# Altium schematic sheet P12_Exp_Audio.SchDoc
size A2
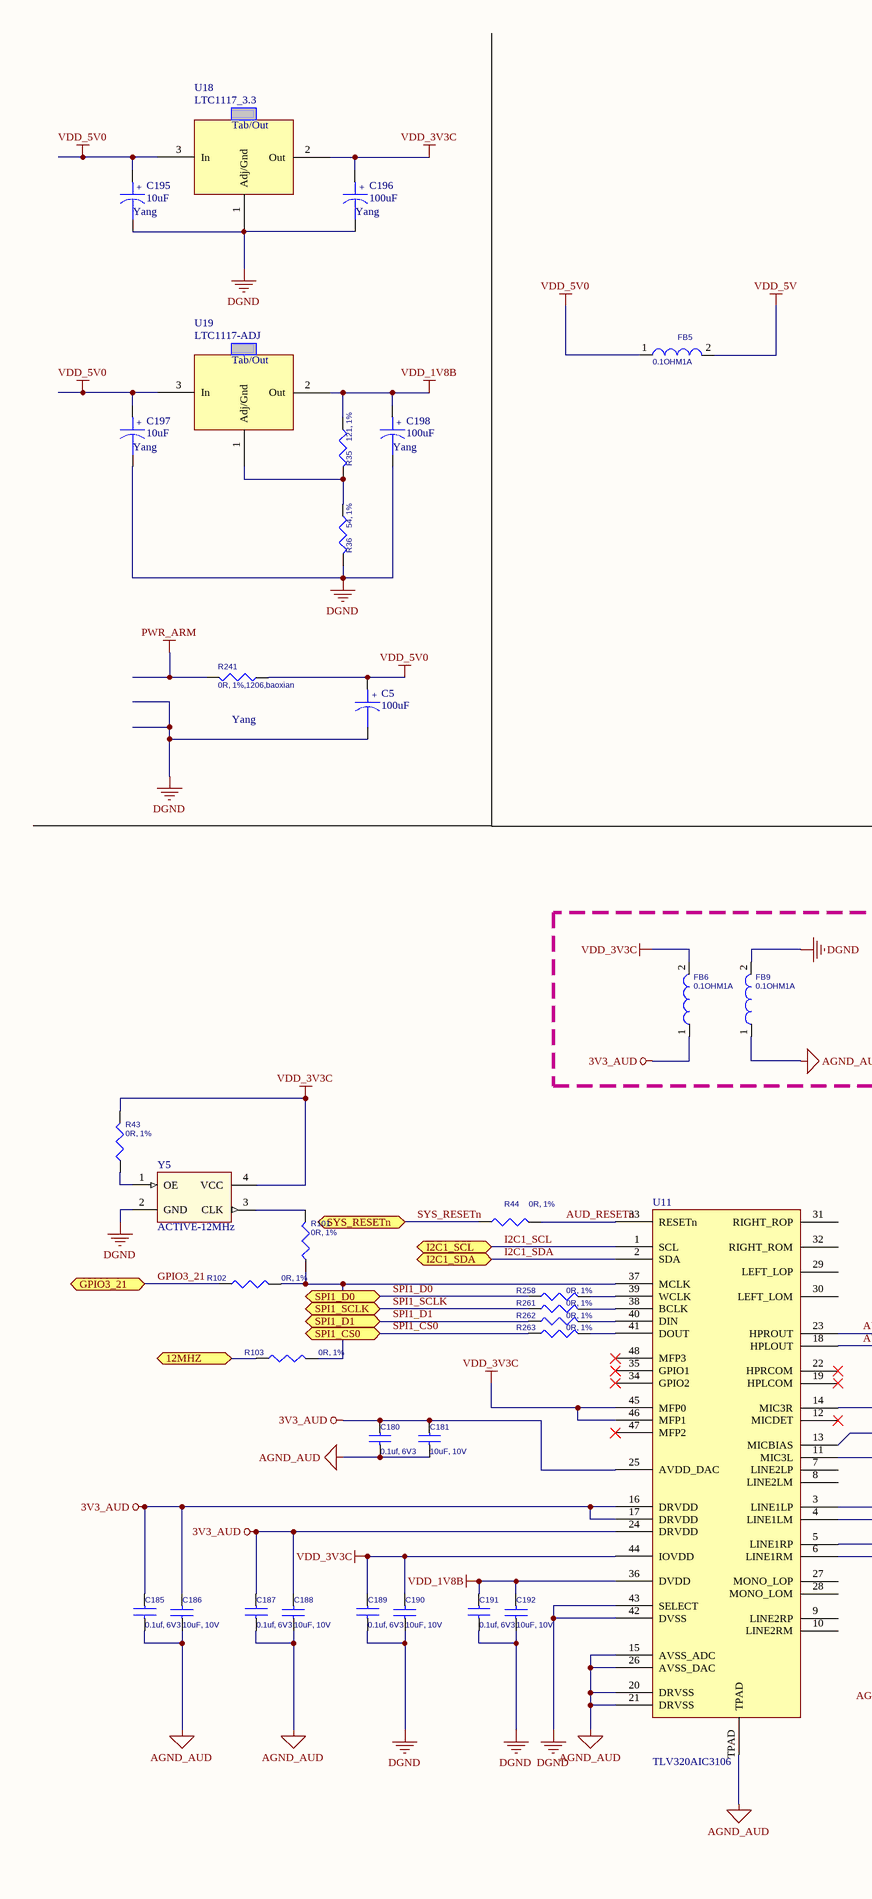
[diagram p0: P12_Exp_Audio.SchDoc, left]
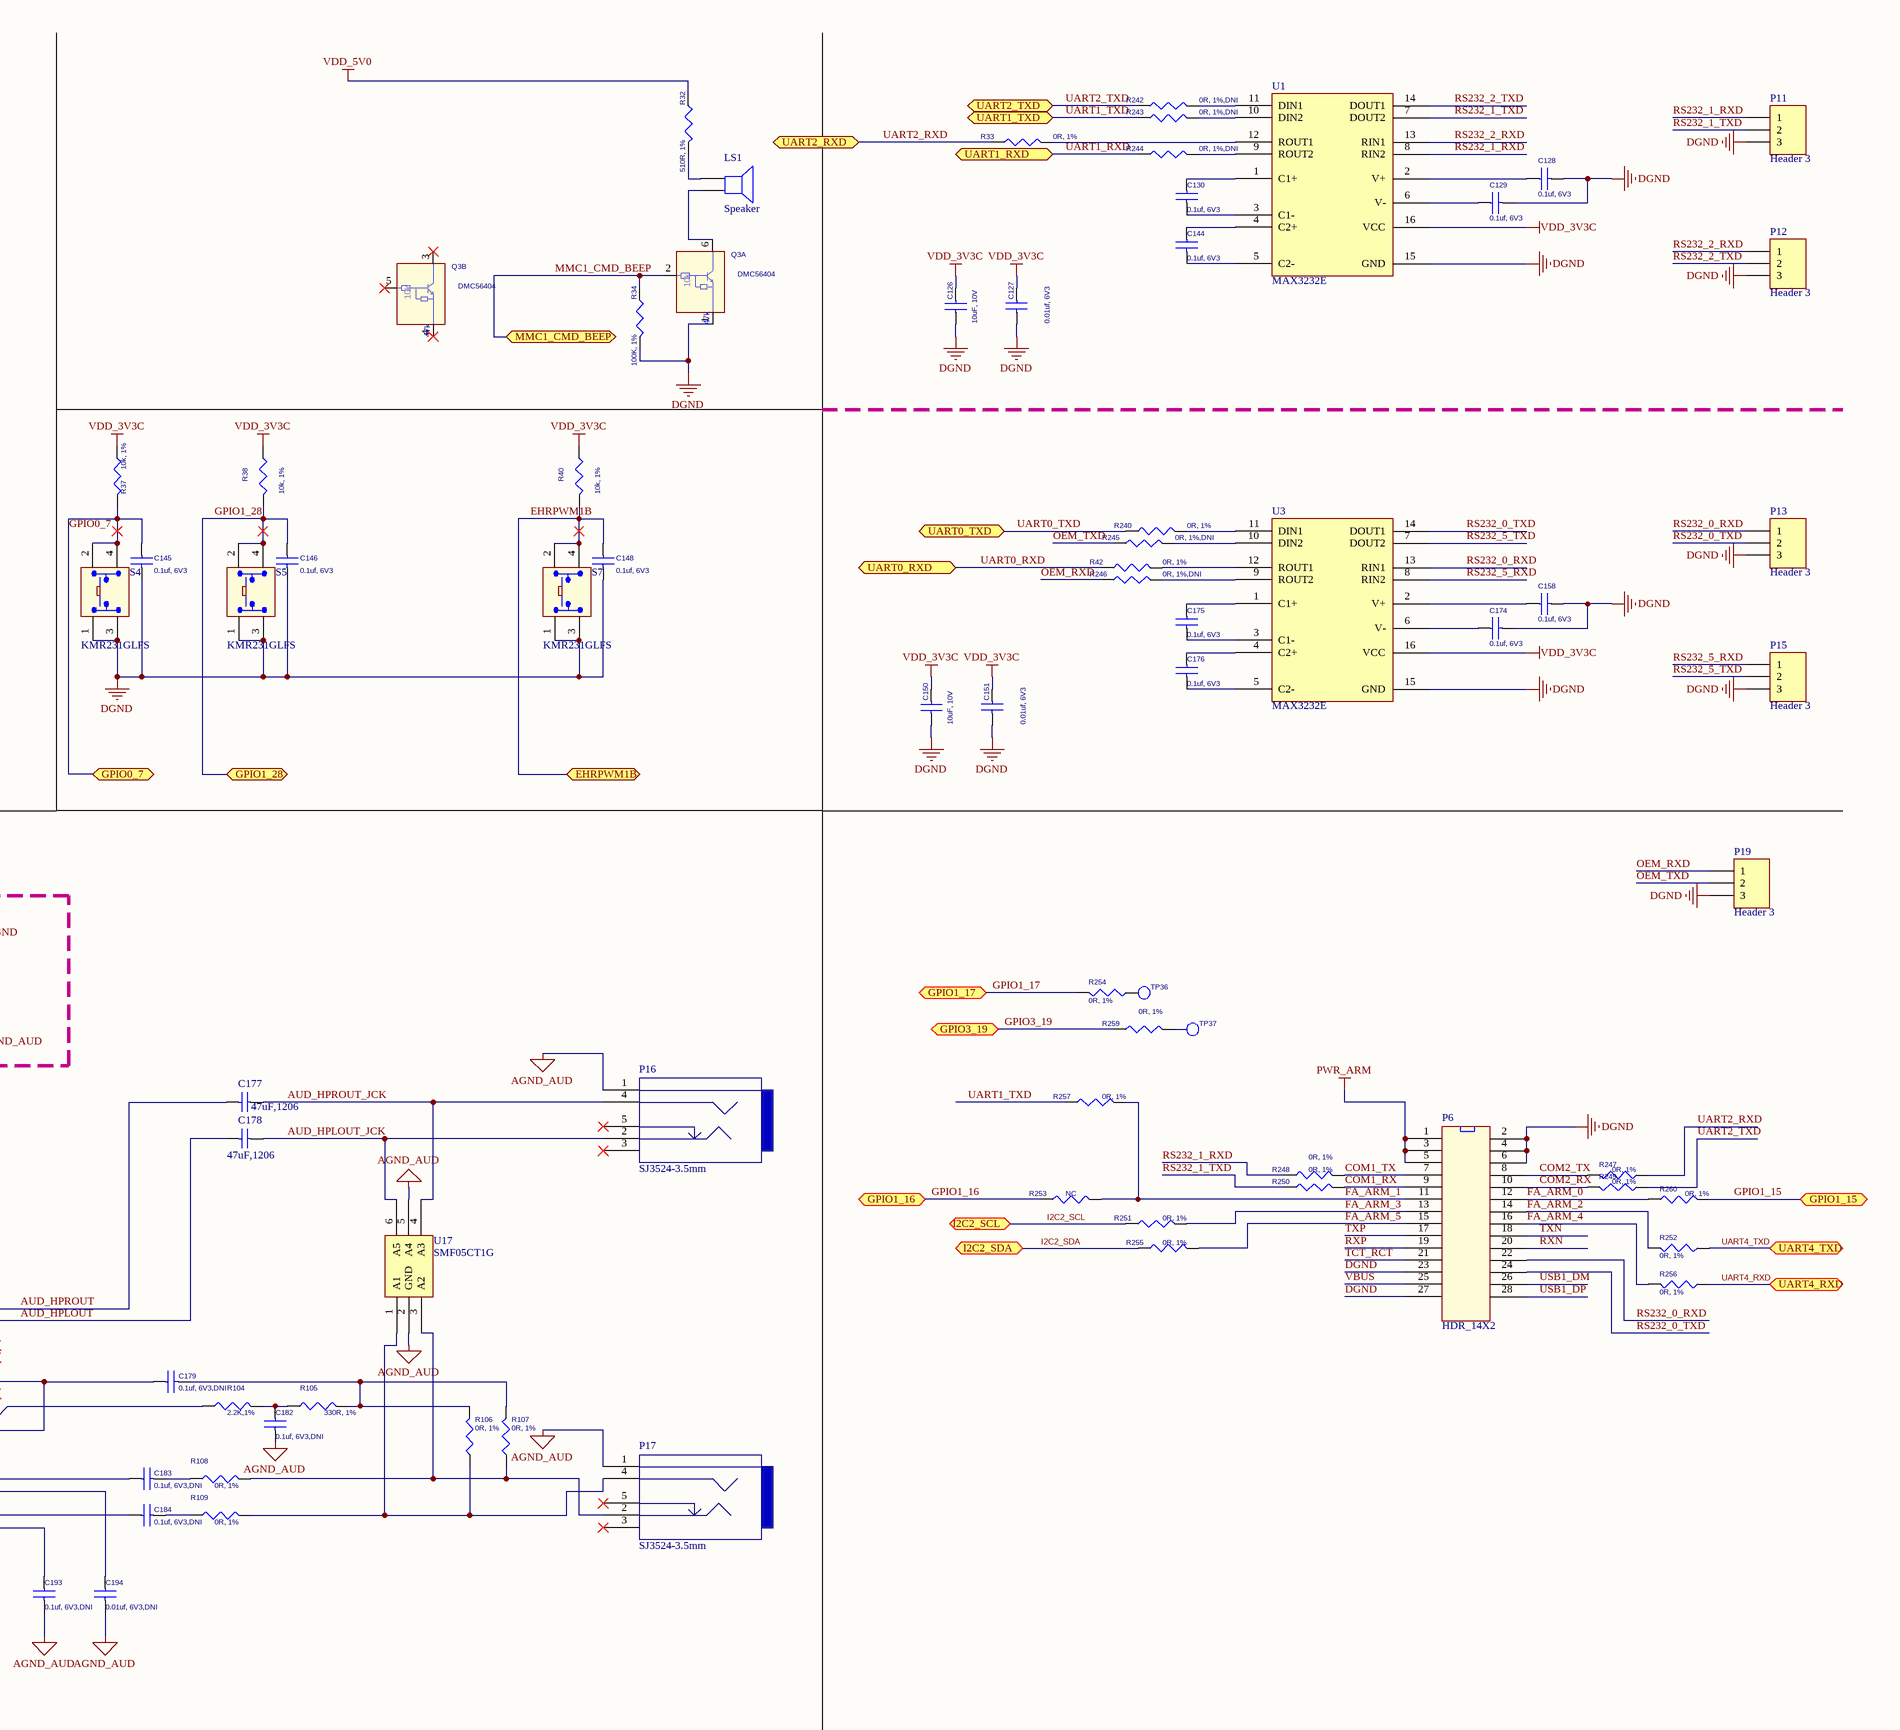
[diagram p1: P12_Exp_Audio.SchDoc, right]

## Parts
C5  100uF  [7343T]
C126  10uF, 10V  [805]
C127  0.01uf, 6V3  [402]
C128  0.1uf, 6V3  [402]
C129  0.1uf, 6V3  [402]
C130  0.1uf, 6V3  [402]
C144  0.1uf, 6V3  [402]
C145  0.1uf, 6V3  [402]
C146  0.1uf, 6V3  [402]
C148  0.1uf, 6V3  [402]
C150  10uF, 10V  [805]
C151  0.01uf, 6V3  [402]
C158  0.1uf, 6V3  [402]
C174  0.1uf, 6V3  [402]
C175  0.1uf, 6V3  [402]
C176  0.1uf, 6V3  [402]
C177  47uF,1206  [1206]
C178  47uF,1206  [1206]
C179  0.1uf, 6V3,DNI  [402]
C180  0.1uf, 6V3  [402]
C181  10uF, 10V  [805]
C182  0.1uf, 6V3,DNI  [402]
C183  0.1uf, 6V3,DNI  [402]
C184  0.1uf, 6V3,DNI  [402]
C185  0.1uf, 6V3  [402]
C186  10uF, 10V  [805]
C187  0.1uf, 6V3  [402]
C188  10uF, 10V  [805]
C189  0.1uf, 6V3  [402]
C190  10uF, 10V  [805]
C191  0.1uf, 6V3  [402]
C192  10uF, 10V  [805]
C193  0.1uf, 6V3,DNI  [402]
C194  0.01uf, 6V3,DNI  [402]
C195  10uF  [3528T]
C196  100uF  [7343T]
C197  10uF  [3528T]
C198  100uF  [7343T]
FB5  0.1OHM1A  [SM-7351-IND-0805]
FB6  0.1OHM1A  [SM-7351-IND-0805]
FB9  0.1OHM1A  [SM-7351-IND-0805]
LS1  Speaker  [PIN2]
P6  HDR_14X2  [HDR_14X2]
P11  Header 3  [HDR1X3]
P12  Header 3  [HDR1X3]
P13  Header 3  [HDR1X3]
P15  Header 3  [HDR1X3]
P16  SJ3524-3.5mm  [jack_audio1]
P17  SJ3524-3.5mm  [jack_audio1]
P19  Header 3  [HDR1X3]
Q3  DMC56404  [SMini6-F3-B]  (parts A,B of 2)
R32  510R, 1%  [R0402]
R33  0R, 1%  [R0603]
R34  100K, 1%  [R0402]
R35  121, 1%  [R0402]
R36  54, 1%  [R0402]
R37  10k, 1%  [R0402]
R38  10k, 1%  [R0402]
R40  10k, 1%  [R0402]
R42  0R, 1%  [R0603]
R43  0R, 1%  [R0402]
R44  0R, 1%  [R0402]
R101  0R, 1%  [R0402]
R102  0R, 1%  [R0402]
R103  0R, 1%  [R0402]
R104  2.2K,1%  [R0402]
R105  330R, 1%  [R0402]
R106  0R, 1%  [R0402]
R107  0R, 1%  [R0402]
R108  0R, 1%  [R0402]
R109  0R, 1%  [R0402]
R240  0R, 1%  [R0603]
R241  0R, 1%,1206,baoxian  [R1206]
R242  0R, 1%,DNI  [R0603]
R243  0R, 1%,DNI  [R0603]
R244  0R, 1%,DNI  [R0603]
R245  0R, 1%,DNI  [R0603]
R246  0R, 1%,DNI  [R0603]
R247  0R, 1%  [R0603]
R248  0R, 1%  [R0603]
R249  0R, 1%  [R0603]
R250  0R, 1%  [R0603]
R251  0R, 1%  [R0603]
R252  0R, 1%  [R0603]
R253  NC  [R0603]
R254  0R, 1%  [R0603]
R255  0R, 1%  [R0603]
R256  0R, 1%  [R0603]
R257  0R, 1%  [R0603]
R258  0R, 1%  [R0603]
R259  0R, 1%  [R0603]
R260  0R, 1%  [R0603]
R261  0R, 1%  [R0603]
R262  0R, 1%  [R0603]
R263  0R, 1%  [R0603]
S4  KMR231GLFS  [SW4SMD_63X161LS]
S5  KMR231GLFS  [SW4SMD_63X161LS]
S7  KMR231GLFS  [SW4SMD_63X161LS]
TP36  TESTPT1  [tp1-8040]  (value not drawn)  (no BOM)
TP37  TESTPT1  [tp1-8040]  (value not drawn)  (no BOM)
U1  MAX3232E  [MAX3232EEA/SSOP16]
U3  MAX3232E  [MAX3232EEA/SSOP16]
U11  TLV320AIC3106  [TLV320AIC3106/QFN-48]
U17  SMF05CT1G  [SMF05CT1G/SC-88]
U18  LTC1117_3.3  [SOT223]
U19  LTC1117-ADJ  [SOT223]
Y5  ACTIVE-12MHz  [OSC4_61X65LS_79X98SMD]

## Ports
12MHZ (bidir), EHRPWM1B (bidir), GPIO0_7 (bidir), GPIO1_15, GPIO1_16, GPIO1_17, GPIO1_28 (bidir), GPIO3_19, GPIO3_21 (bidir), I2C1_SCL (bidir), I2C1_SDA (bidir), I2C2_SCL, I2C2_SDA, MMC1_CMD_BEEP (bidir), SPI1_CS0 (bidir), SPI1_D0 (bidir), SPI1_D1 (bidir), SPI1_SCLK (bidir), SYS_RESETn (bidir), UART0_RXD (bidir), UART0_TXD (bidir), UART1_RXD (bidir), UART1_TXD (bidir), UART2_RXD (bidir), UART2_TXD (bidir), UART4_RXD, UART4_TXD

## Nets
3V3_AUD: C180.1 C181.1 C185.1 C186.2 C187.1 C188.2 FB6.1 U11.16(DRVDD) U11.17(DRVDD) U11.24(DRVDD) U11.25(AVDD_DAC)
AGND_AUD: C180.2 C181.2 C182.2 C185.2 C186.1 C187.2 C188.1 C193.2 C194.2 FB9.1 P16.1 P17.1 U11.15(AVSS_ADC) U11.20(DRVSS) U11.21(DRVSS) U11.26(AVSS_DAC) U11.TPAD U17.2(GND) U17.5(A4)
DGND: C5.2 C126.1 C127.2 C128.2 C129.2 C145.2 C146.2 C148.2 C150.1 C151.2 C158.2 C174.2 C189.2 C190.1 C191.2 C192.1 C195.2 C196.2 C197.2 C198.2 FB9.2 P6.2 P6.4 P6.6 P6.23 P6.27 P11.3 P12.3 P13.3 P15.3 P19.3 Q3.1 R34.2 R36.2 S4.1(A1) S4.3(A3) S5.1(A1) S5.3(A3) S7.1(A1) S7.3(A3) U1.15(GND) U3.15(GND) U11.42(DVSS) U11.43(SELECT) U18.1(Adj/Gnd) Y5.2(GND)
PWR_ARM: P6.1 P6.3 P6.5 R241.2
VDD_1V8B: C191.1 C192.2 C198.1 R35.1 U11.36(DVDD) U19.2(Out)
VDD_3V3C: C126.2 C127.1 C150.2 C151.1 C189.1 C190.2 C196.1 FB6.2 R37.1 R38.1 R40.1 R43.2 U1.16(VCC) U3.16(VCC) U11.44(IOVDD) U11.45(MFP0) U11.46(MFP1) U18.2(Out) Y5.4(VCC)
VDD_5V: FB5.2
VDD_5V0: C5.1 C195.1 C197.1 FB5.1 R32.1 R241.1 U18.3(In) U19.3(In)
12MHZ: R103.1 ; port 12MHZ
AUD_HPLOUT: C178.2 U11.18(HPLOUT)
AUD_HPLOUT_JCK: C178.1 P16.2 U17.6(A5)
AUD_HPROUT: C177.2 U11.23(HPROUT)
AUD_HPROUT_JCK: C177.1 P16.4 U17.4(A3)
AUD_RESETn: R44.2 U11.33(RESETn)
COM1_RX: P6.9 R250.2
COM1_TX: P6.7 R248.2
COM2_RX: P6.10 R249.2
COM2_TX: P6.8 R247.2
EHRPWM1B: C148.1 R40.2 S7.2(A2) S7.4 ; port EHRPWM1B
FA_ARM_0: P6.12 R260.1
FA_ARM_1: P6.11 R253.2 R257.2
FA_ARM_2: P6.14 R252.2
FA_ARM_3: P6.13 R251.2
FA_ARM_4: P6.16 R256.2
FA_ARM_5: P6.15 R255.2
GPIO0_7: C145.1 R37.2 S4.2(A2) S4.4 ; port GPIO0_7
GPIO1_15: R260.2 ; port GPIO1_15
GPIO1_16: R253.1 ; port GPIO1_16
GPIO1_17: R254.2 ; port GPIO1_17
GPIO1_28: C146.1 R38.2 S5.2(A2) S5.4 ; port GPIO1_28
GPIO3_19: R259.1 ; port GPIO3_19
GPIO3_21: R102.1 ; port GPIO3_21
I2C1_SCL: U11.1(SCL) ; port I2C1_SCL
I2C1_SDA: U11.2(SDA) ; port I2C1_SDA
I2C2_SCL: R251.1 ; port I2C2_SCL
I2C2_SDA: R255.1 ; port I2C2_SDA
MMC1_CMD_BEEP: Q3.2 R34.1 ; port MMC1_CMD_BEEP
OEM_RXD: P19.1 R246.1
OEM_TXD: P19.2 R245.1
RS232_0_RXD: P6.22 P13.1 U3.13(RIN1)
RS232_0_TXD: P6.24 P13.2 U3.14(DOUT1)
RS232_1_RXD: P11.1 R248.1 U1.8(RIN2)
RS232_1_TXD: P11.2 R250.1 U1.7(DOUT2)
RS232_2_RXD: P12.1 U1.13(RIN1)
RS232_2_TXD: P12.2 U1.14(DOUT1)
RS232_5_RXD: P15.1 U3.8(RIN2)
RS232_5_TXD: P15.2 U3.7(DOUT2)
RXN: P6.20
RXP: P6.19
SPI1_CS0: R263.1 ; port SPI1_CS0
SPI1_D0: R258.1 ; port SPI1_D0
SPI1_D1: R262.1 ; port SPI1_D1
SPI1_SCLK: R261.1 ; port SPI1_SCLK
SYS_RESETn: R44.1 ; port SYS_RESETn
TCT_RCT: P6.21
TXN: P6.18
TXP: P6.17
UART0_RXD: R42.1 ; port UART0_RXD
UART0_TXD: R240.1 ; port UART0_TXD
UART1_RXD: R244.1 ; port UART1_RXD
UART1_TXD: R243.1 R257.1 ; port UART1_TXD
UART2_RXD: R33.1 R247.1 ; port UART2_RXD
UART2_TXD: R242.1 R249.1 ; port UART2_TXD
UART4_RXD: R256.1 ; port UART4_RXD
UART4_TXD: R252.1 ; port UART4_TXD
USB1_DM: P6.26
USB1_DP: P6.28
VBUS: P6.25
NetC128_1: C128.1 U1.2(V+)
NetC129_1: C129.1 U1.6(V-)
NetC130_1: C130.1 U1.1(C1+)
NetC130_2: C130.2 U1.3(C1-)
NetC144_1: C144.1 U1.4(C2+)
NetC144_2: C144.2 U1.5(C2-)
NetC158_1: C158.1 U3.2(V+)
NetC174_1: C174.1 U3.6(V-)
NetC175_1: C175.1 U3.1(C1+)
NetC175_2: C175.2 U3.3(C1-)
NetC176_1: C176.1 U3.4(C2+)
NetC176_2: C176.2 U3.5(C2-)
NetC179_1: C179.1 U11.11(MIC3L) U11.14(MIC3R)
NetC179_2: C179.2 R105.2 R106.2 R107.2
NetC182_1: C182.1 R104.2 R105.1
NetC183_1: C183.1 U11.3(LINE1LP)
NetC183_2: C183.2 R108.1
NetC184_1: C184.1 U11.5(LINE1RP)
NetC184_2: C184.2 R109.1
NetC193_1: C193.1 U11.6(LINE1RM)
NetC194_1: C194.1 U11.4(LINE1LM)
NetLS1_1: LS1.1 R32.2
NetLS1_2: LS1.2 Q3.6
NetP17_2: P17.2 R107.1 R108.2 U17.3(A2)
NetP17_4: P17.4 R106.1 R109.2 U17.1(A1)
NetR33_2: R33.2 U1.12(ROUT1)
NetR35_2: R35.2 R36.1 U19.1(Adj/Gnd)
NetR42_2: R42.2 U3.12(ROUT1)
NetR43_1: R43.1 Y5.1(OE)
NetR101_1: R101.1 R102.2 R103.2 U11.37(MCLK)
NetR101_2: R101.2 Y5.3(CLK)
NetR104_1: R104.1 U11.13(MICBIAS)
NetR240_2: R240.2 U3.11(DIN1)
NetR242_2: R242.2 U1.11(DIN1)
NetR243_2: R243.2 U1.10(DIN2)
NetR244_2: R244.2 U1.9(ROUT2)
NetR245_2: R245.2 U3.10(DIN2)
NetR246_2: R246.2 U3.9(ROUT2)
NetR254_1: R254.1 TP36.1(TP)
NetR258_2: R258.2 U11.39(WCLK)
NetR259_2: R259.2 TP37.1(TP)
NetR261_2: R261.2 U11.38(BCLK)
NetR262_2: R262.2 U11.40(DIN)
NetR263_2: R263.2 U11.41(DOUT)

Not connected (* = marked no-connect by the designer): P16 3* 5*; P17 3* 5*; Q3 3* 4* 5*; U11 7(LINE2LP) 8(LINE2LM) 9(LINE2RP) 10(LINE2RM) 12(MICDET)* 19(HPLCOM)* 22(HPRCOM)* 27(MONO_LOP) 28(MONO_LOM) 29(LEFT_LOP) 30(LEFT_LOM) 31(RIGHT_ROP) 32(RIGHT_ROM) 34(GPIO2)* 35(GPIO1)* 47(MFP2)* 48(MFP3)*

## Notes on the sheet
- (near C195) Yang
- (near C196) Yang
- (near C197) Yang
- (near C198) Yang
- (near R241) Yang

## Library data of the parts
C5 C195-C198 = CAPACITOR POL: Capacitor
C126 C150 C181 C186 C188 C190 C192 = CAP_10uF_Y5V_10V_10%_0805: CAP CER 10UF 10V Y5V 0805; Manufacturer: TDK Corporation; Manufacturer Part Number: C2012Y5V1A106Z; Capacitance: 10µF; Tolerance: -20%, +80%; Temperature Coefficient: Y5V (F)
C127-C130 C144-C146 C148 C151 C158 C174-C176 C179 C180 C182-C185 C187 C189 C191 C193 C194 = CAP_0.1uF_X7R_16V_10% 0402: CAP CER 0.1UF 6.3V 10% X5R 0402; Manufacturer: TDK Corporation; Manufacturer Part Number: C1005X5R0J104K050BA; Capacitance: 0.1µF; Tolerance: ?0%
C177 C178 = Cap: Capacitor
FB5 FB6 FB9 = FER_180_200_0: FERRITE 800MA 150 OHM 0805 SMD; PartName: FerriteBead150ohm800mA; Mfr: Steward; MfrNum: LI0805H151R-10; TIIntPartnumber: 1L0010; Manufacturer: Laird-Signal Integrity Products; Vendor: Digikey; Impedance @ Frequency: 150 Ohm @ 100MHz; DC Resistance (DCR): 150 mOhm Max; Filter Type: Differential Mode - Single
LS1 = Speaker: Loudspeaker
P11-P13 P15 P19 = Header 3: Header, 3-Pin
Q3 = RN1907: TRANS PREBIASED DUAL NPN SOT363; Manufacturer: Toshiba; Manufacturer Part Number: DDC114YU-7-F; Order# 2: BCR135S; ATLStockNo1: 2130.0137; ATLStockNo2: 2130.01; Transistor Type: 2 NPN - Pre-Biased (Dual); Current - Collector (Ic) (Max): 100mA; Voltage - Collector Emitter Breakdown (Max): 50V; Resistor - Base (R1) (Ohms): 10k; Resistor - Emitter Base (R2) (Ohms): 47k; DC Current Gain (hFE) (Min) @ Ic, Vce: 68 @ 10mA, 5V; Vce Saturation (Max) @ Ib, Ic: 300mV @ 250µA, 5mA; Current - Collector Cutoff (Max): 500nA; Frequency - Transition: 250MHz; Power - Max: 200mW
R32 R34 = RES_100K_1/16W_1%_0402: RES 100K OHM 1/16W 1% 0402 SMD; Manufacturer: Stackpole Electronics Inc; Manufacturer Part Number: RMCF0402FT100K; Power (Watts): 0.063W, 1/16W; Temperature Coefficient: ?00ppm/°C; Tolerance: ?%
R33 R42-R44 R101-R109 R240 = RES_0_1/16W_1%_0402: RES 0.0 OHM 1/16W 0402 SMD; Manufacturer: Yageo; Manufacturer Part Number: RC0402JR-070RL; Resistance (Ohms): 0.0; Power (Watts): 0.063W, 1/16W; Tolerance: Jumper
R35-R38 R40 = RES_10K_1/16W_1%_0402: RES 10K OHM 1/16W 5% 0402 SMD; Manufacturer: Rohm Semiconductor; Manufacturer Part Number: MCR01MZPJ103; Power (Watts): 0.063W, 1/16W; Temperature Coefficient: ?00ppm/°C; Tolerance: ?%
R241 = RES_470_1/10W_5%_0402: RES 470K OHM 1/16W 1% 0402 SMD; Manufacturer: Yageo; Manufacturer Part Number: RC0402FR-07470KL; Power (Watts): 0.063W, 1/16W; Temperature Coefficient: ?00ppm/°C; Tolerance: ?%
R242-R245 = RES_0_1/16W_1%_0402: RES 0.0 OHM,0603; Manufacturer: Yageo; Manufacturer Part Number: RC0402JR-070RL; Resistance (Ohms): 0.0; Power (Watts): 0.063W, 1/16W; Tolerance: Jumper
R246-R263 = RES_0_1/16W_1%_0402: RES 0.0 OHM,0603,DNI; Manufacturer: Yageo; Manufacturer Part Number: RC0402JR-070RL; Resistance (Ohms): 0.0; Power (Watts): 0.063W, 1/16W; Tolerance: Jumper
S4 S5 S7 = KMR2: Microminiature Tact Switch for SMT; Manufacturer: C&K Components; Circuit: SPST-NO; Switch Function: Off-Mom; Contact Rating @ Voltage: 0.05A @ 32VDC; Actuator Type: Standard; Actuator Height off PCB, from Pins: 1.90mm; Actuator Orientation: Top Actuated; Outline: 4.60mm x 2.80mm; Illumination: Non-Illuminated; Operating Force: 300gf; Switch Travel: 0.25mm; Mechanical Life: 150,000 Cycles
U18 U19 = AMS1117_X
Y5 = ASDMB: Manufacturer: Abracon Corporation; Manufacturer Part Number: ASDMB-24.576MHZ-LC-T; Frequency: 24.576MHz; Function: Standby (Power Down); Output: CMOS; Voltage - Supply: 1.8 V ~ 3.3 V; Frequency Stability: ?0ppm; Current - Supply (Max): 16mA; Current - Supply (Disable) (Max): 15µA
